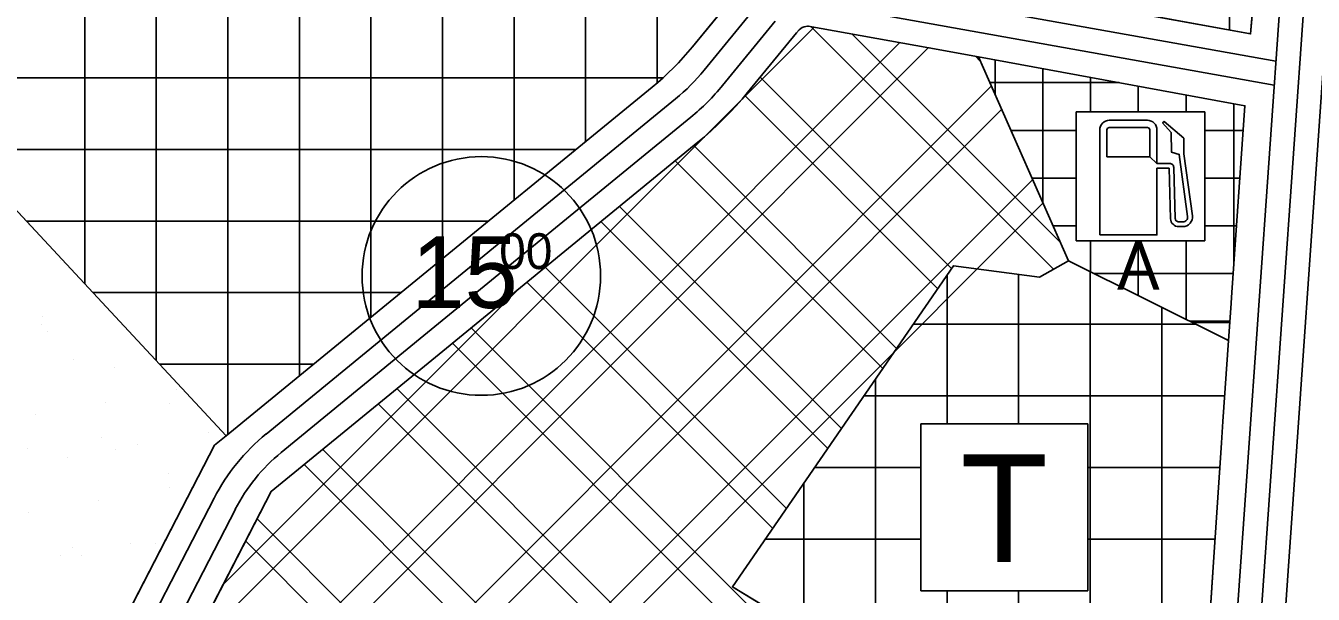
# Model space of a CAD drawing. Extents: x 419109 to 421295, y 4452223 to 4457798.
# Drawn here: x 419929.3 to 420199.2, y 4455078.6 to 4455197.7 of the extents above; entities that cross this region are included whole.
import ezdxf

# ---------------------------------------------------------------- set-up
doc = ezdxf.new("R2010")
doc.units = 0
for name, color, linetype in [('ADAKENARI', 7, 'Continuous'), ('KALDIRIM_FAT', 7, 'Continuous'), ('KD_DAIRE', 7, 'Continuous'), ('KD_YGEN', 7, 'Continuous'), ('PL_AYA_PARK_DINLENME', 7, 'Continuous'), ('PL_BAKIM_AKARYAKIT', 7, 'Continuous'), ('PL_K_DEPOLAMA', 7, 'Continuous'), ('PL_TİCARET', 7, 'Continuous'), ('SEMBOL_FAT', 7, 'Continuous'), ('TRFAT_AKARYAKITSERVİ', 7, 'Continuous'), ('TRFAT_DEPOLAMA', 7, 'Continuous'), ('TRFAT_PARKALANI', 7, 'Continuous'), ('TRFAT_TİCARET', 7, 'Continuous')]:
    doc.layers.add(name, color=color, linetype=linetype)

msp = doc.modelspace()

# ---------------------------------------------------------------- linework, layer by layer
at = {"layer": 'ADAKENARI'}
for p, q in [((420188.54, 4455224.54), (420186.09, 4455195.96)), ((420121.64, 4455207.8), (420186.09, 4455195.96)), ((420069.08, 4455193.26), (420079.57, 4455206.07)), ((420090.86, 4455196.18), (420091.47, 4455196.83)), ((420091.47, 4455196.83), (420091.78, 4455197.08)), ((420091.78, 4455197.08), (420092.11, 4455197.29)), ((420092.11, 4455197.29), (420092.48, 4455197.45)), ((420092.48, 4455197.45), (420092.85, 4455197.56)), ((420092.85, 4455197.56), (420093.2, 4455197.61)), ((420093.2, 4455197.61), (420093.34, 4455197.61)), ((420093.34, 4455197.61), (420118.65, 4455193.09)), ((420080.63, 4455183.68), (420090.86, 4455196.18)), ((420067.13, 4455191), (420068.12, 4455192.12)), ((420068.12, 4455192.12), (420069.08, 4455193.26)), ((420118.65, 4455193.09), (420129.01, 4455191.19)), ((420129.01, 4455191.19), (420147.88, 4455148.42)), ((420129.01, 4455191.19), (420184.88, 4455180.93)), ((420064.01, 4455187.8), (420065.08, 4455188.84)), ((420065.08, 4455188.84), (420066.12, 4455189.91)), ((420066.12, 4455189.91), (420067.13, 4455191)), ((420060.66, 4455184.84), (420061.8, 4455185.8)), ((420061.8, 4455185.8), (420062.92, 4455186.78)), ((420062.92, 4455186.78), (420064.01, 4455187.8)), ((419931.39, 4455154.69), (419902.86, 4455185.32)), ((420006.47, 4455140.52), (420060.66, 4455184.84)), ((420079.49, 4455182.33), (420080.63, 4455183.68)), ((420076.98, 4455179.56), (420078.25, 4455180.93)), ((420078.25, 4455180.93), (420079.49, 4455182.33)), ((420184.88, 4455180.93), (420182.14, 4455141.79)), ((420074.35, 4455176.93), (420075.68, 4455178.23)), ((420075.68, 4455178.23), (420076.98, 4455179.56)), ((420071.58, 4455174.43), (420072.98, 4455175.66)), ((420072.98, 4455175.66), (420074.35, 4455176.93)), ((420015.97, 4455128.91), (420070.23, 4455173.29)), ((420070.23, 4455173.29), (420071.58, 4455174.43)), ((419971.34, 4455111.77), (419931.39, 4455154.69)), ((420141.8, 4455145.02), (420147.88, 4455148.42)), ((420147.88, 4455148.42), (420181.44, 4455131.77)), ((420077.46, 4455080.1), (420123.77, 4455147.42)), ((420123.77, 4455147.42), (420141.8, 4455145.02)), ((420006.47, 4455140.52), (419971.34, 4455111.77)), ((420182.14, 4455141.79), (420181.91, 4455138.55)), ((420181.91, 4455138.55), (420181.44, 4455131.77)), ((420181.44, 4455131.77), (420180.25, 4455114.78)), ((420015.97, 4455128.91), (419980.79, 4455100.13)), ((420180.25, 4455114.78), (420179.97, 4455110.31)), ((419971.34, 4455111.77), (419968.89, 4455109.78)), ((420179.97, 4455110.31), (420178.23, 4455084.23)), ((419968.89, 4455109.78), (419932.03, 4455038.44)), ((419980.79, 4455100.13), (419945.05, 4455030.94)), ((420178.23, 4455084.23), (420176.33, 4455055.75)), ((420135.16, 4455045.14), (420077.46, 4455080.1))]:
    msp.add_line(p, q, dxfattribs=at)
at = {"layer": 'KALDIRIM_FAT'}
for p, q in [((420215.94, 4455540.77), (420179.4, 4455019.05)), ((420220.93, 4455540.45), (420184.39, 4455018.74)), ((420225.92, 4455540.14), (420189.38, 4455018.43)), ((420096.91, 4455207.13), (420191.39, 4455190.25)), ((420096.03, 4455202.21), (420191.04, 4455185.24)), ((420071.54, 4455188.37), (420082.57, 4455201.84)), ((420075.41, 4455185.2), (420086.44, 4455198.67)), ((420009.64, 4455136.65), (420065.55, 4455182.38)), ((420012.8, 4455132.78), (420068.71, 4455178.51)), ((420009.64, 4455136.65), (419979.7, 4455112.15)), ((420012.8, 4455132.78), (419982.86, 4455108.28)), ((419968.81, 4455098.71), (419937.11, 4455037.35)), ((419973.25, 4455096.42), (419941.56, 4455035.06))]:
    msp.add_line(p, q, dxfattribs=at)
for centre, radius, start, end in [((420038.54, 4455215.4), 42.66, 309.2838, 320.6835), ((420038.54, 4455215.4), 47.66, 309.2838, 320.6835), ((420006.71, 4455079.14), 42.66, 129.2845, 152.6835), ((420006.71, 4455079.14), 37.66, 129.2845, 152.6835)]:
    msp.add_arc(centre, radius, start, end, dxfattribs=at)
at = {"layer": 'KD_DAIRE'}
msp.add_circle((420024.82, 4455145.26), 25, dxfattribs=at)
at = {"layer": 'PL_AYA_PARK_DINLENME'}
msp.add_lwpolyline([(419902.86, 4455185.32), (419931.39, 4455154.69), (419971.34, 4455111.77), (419968.89, 4455109.78), (419932.03, 4455038.44), (419931.6, 4455037.58), (419931.19, 4455036.71), (419930.8, 4455035.83), (419930.43, 4455034.94), (419930.09, 4455034.04), (419929.76, 4455033.14), (419929.46, 4455032.22), (419929.18, 4455031.3)], dxfattribs=at)
at = {"layer": 'PL_BAKIM_AKARYAKIT'}
msp.add_lwpolyline([(420182.14, 4455141.79), (420181.91, 4455138.55), (420181.44, 4455131.77), (420147.88, 4455148.42), (420129.01, 4455191.19), (420184.88, 4455180.93)], close=True, dxfattribs=at)
at = {"layer": 'PL_K_DEPOLAMA'}
msp.add_lwpolyline([(420135.16, 4455045.14), (420077.46, 4455080.1), (420123.77, 4455147.42), (420141.8, 4455145.02), (420147.88, 4455148.42), (420129.01, 4455191.19), (420118.65, 4455193.09), (420093.34, 4455197.61), (420093.2, 4455197.61), (420092.85, 4455197.56), (420092.48, 4455197.45), (420092.11, 4455197.29), (420091.78, 4455197.08), (420091.47, 4455196.83), (420090.86, 4455196.18), (420080.63, 4455183.68), (420079.49, 4455182.33), (420078.25, 4455180.93), (420076.98, 4455179.56), (420075.68, 4455178.23), (420074.35, 4455176.93), (420072.98, 4455175.66), (420071.58, 4455174.43), (420070.23, 4455173.29), (420015.97, 4455128.91), (419980.79, 4455100.13), (419945.05, 4455030.94)], dxfattribs=at)
at = {"layer": 'PL_TİCARET'}
for points in [[(419815.33, 4455292.01), (419836.87, 4455182.74), (419902.86, 4455185.32), (419931.39, 4455154.69), (419971.34, 4455111.77), (420006.47, 4455140.52), (420060.66, 4455184.84), (420061.8, 4455185.8), (420062.92, 4455186.78), (420064.01, 4455187.8), (420065.08, 4455188.84), (420066.12, 4455189.91), (420067.13, 4455191), (420068.12, 4455192.12), (420069.08, 4455193.26), (420079.57, 4455206.07)], [(420121.64, 4455207.8), (420186.09, 4455195.96), (420188.54, 4455224.54)]]:
    msp.add_lwpolyline(points, dxfattribs=at)
msp.add_lwpolyline([(420147.88, 4455148.42), (420181.44, 4455131.77), (420180.25, 4455114.78), (420179.97, 4455110.31), (420178.23, 4455084.23), (420176.33, 4455055.75), (420158.29, 4455055.9), (420147.48, 4455061.78), (420143.45, 4455057.26), (420135.16, 4455045.14), (420077.46, 4455080.1), (420123.77, 4455147.42), (420141.8, 4455145.02)], close=True, dxfattribs=at)
at = {"layer": 'SEMBOL_FAT'}
for p, q in [((420149.51, 4455179.63), (420149.51, 4455152.63)), ((420149.51, 4455179.63), (420176.51, 4455179.63)), ((420176.51, 4455179.63), (420176.51, 4455152.63)), ((420149.51, 4455152.63), (420176.51, 4455152.63)), ((420116.94, 4455114.29), (420116.94, 4455079.29)), ((420116.94, 4455114.29), (420151.94, 4455114.29)), ((420151.94, 4455114.29), (420151.94, 4455079.29)), ((420116.94, 4455079.29), (420151.94, 4455079.29))]:
    msp.add_line(p, q, dxfattribs=at)
msp.add_lwpolyline([(420154.46, 4455153.87), (420154.46, 4455175.87), (420154.5, 4455176.26), (420154.61, 4455176.63), (420154.8, 4455176.98), (420155.05, 4455177.28), (420155.35, 4455177.53), (420155.69, 4455177.71), (420156.07, 4455177.83), (420156.46, 4455177.87), (420164.46, 4455177.87), (420164.85, 4455177.83), (420165.22, 4455177.71), (420165.57, 4455177.53), (420165.87, 4455177.28), (420166.12, 4455176.98), (420166.31, 4455176.63), (420166.42, 4455176.26), (420166.46, 4455175.87), (420166.46, 4455168.84), (420164.96, 4455170.23), (420164.96, 4455175.87), (420164.81, 4455176.22), (420164.46, 4455176.37), (420156.46, 4455176.37), (420156.11, 4455176.22), (420155.96, 4455175.87), (420155.96, 4455170.23), (420164.96, 4455170.23), (420166.46, 4455168.84), (420169.13, 4455168.84), (420169.29, 4455168.82), (420169.45, 4455168.78), (420169.59, 4455168.7), (420169.72, 4455168.6), (420169.82, 4455168.48), (420169.9, 4455168.34), (420169.95, 4455168.18), (420169.97, 4455168.02), (420170.3, 4455157.27), (420170.32, 4455157.14), (420170.36, 4455157.01), (420170.43, 4455156.9), (420170.51, 4455156.8), (420170.62, 4455156.71), (420170.73, 4455156.65), (420170.86, 4455156.61), (420170.99, 4455156.6), (420171.88, 4455156.6), (420172.09, 4455156.62), (420172.29, 4455156.69), (420172.48, 4455156.8), (420172.64, 4455156.95), (420172.76, 4455157.12), (420172.84, 4455157.32), (420172.88, 4455157.53), (420172.88, 4455157.75), (420171.13, 4455170.72), (420169.49, 4455171.23), (420169.45, 4455175.29), (420167.64, 4455177.34), (420167.94, 4455177.61), (420172.09, 4455174.11), (420172.12, 4455170.85), (420173.87, 4455157.88), (420173.88, 4455157.45), (420173.8, 4455157.03), (420173.64, 4455156.64), (420173.39, 4455156.29), (420173.08, 4455156), (420172.71, 4455155.78), (420172.3, 4455155.65), (420171.88, 4455155.6), (420170.99, 4455155.6), (420170.67, 4455155.63), (420170.36, 4455155.72), (420170.07, 4455155.88), (420169.82, 4455156.08), (420169.6, 4455156.33), (420169.45, 4455156.61), (420169.34, 4455156.92), (420169.3, 4455157.24), (420168.98, 4455167.84), (420166.46, 4455167.84), (420166.46, 4455153.87)], close=True, dxfattribs=at)
at = {"layer": 'TRFAT_AKARYAKITSERVİ'}
for p, q in [((420132.54, 4455190.54), (420132.54, 4455183.18)), ((420142.54, 4455188.7), (420142.54, 4455160.51)), ((420131.4, 4455185.77), (420158.55, 4455185.77)), ((420152.54, 4455186.87), (420152.54, 4455179.63)), ((420162.54, 4455185.03), (420162.54, 4455179.63)), ((420172.54, 4455183.2), (420172.54, 4455179.63)), ((420182.54, 4455181.36), (420182.54, 4455147.61)), ((420135.81, 4455175.77), (420149.51, 4455175.77)), ((420176.51, 4455175.77), (420184.51, 4455175.77)), ((420140.23, 4455165.77), (420149.51, 4455165.77)), ((420176.51, 4455165.77), (420183.81, 4455165.77)), ((420144.64, 4455155.77), (420149.51, 4455155.77)), ((420176.51, 4455155.77), (420183.11, 4455155.77)), ((420152.54, 4455152.63), (420152.54, 4455146.1)), ((420162.54, 4455152.63), (420162.54, 4455141.14)), ((420172.54, 4455152.63), (420172.54, 4455136.18)), ((420153.23, 4455145.77), (420182.42, 4455145.77)), ((420173.38, 4455135.77), (420181.72, 4455135.77)), ((420173.86, 4455135.53), (420181.7, 4455135.53))]:
    msp.add_line(p, q, dxfattribs=at)
at = {"layer": 'TRFAT_DEPOLAMA'}
for p, q in [((419963.15, 4455065.96), (420094.58, 4455197.39)), ((420093.89, 4455197.52), (420144.74, 4455146.66)), ((419942.79, 4455024.39), (420112.57, 4455194.18)), ((420102.5, 4455195.98), (420146.16, 4455152.32)), ((419939.86, 4455014.4), (420118.57, 4455193.11)), ((420128.39, 4455191.3), (420129.41, 4455190.28)), ((420083.28, 4455186.92), (420123.37, 4455146.83)), ((419959.89, 4455013.21), (420131.72, 4455185.04)), ((420080.09, 4455183.04), (420120.48, 4455142.64)), ((419966.89, 4455013.14), (420133.89, 4455180.14)), ((420069.34, 4455172.57), (420111.84, 4455130.07)), ((420065.45, 4455169.38), (420108.96, 4455125.88)), ((420037.87, 4455062.9), (420140.38, 4455165.42)), ((420044.94, 4455062.9), (420142.54, 4455160.51)), ((420053.79, 4455159.84), (420100.31, 4455113.31)), ((420049.9, 4455156.66), (420097.43, 4455109.13)), ((420038.23, 4455147.11), (420088.78, 4455096.56)), ((419970.7, 4455080.59), (420032.71, 4455142.6)), ((420034.34, 4455143.93), (420085.9, 4455092.37)), ((420022.67, 4455134.39), (420125.86, 4455031.2)), ((420018.78, 4455131.21), (420123.03, 4455026.95)), ((420007.11, 4455121.66), (420114.55, 4455014.22)), ((420003.22, 4455118.48), (420110.08, 4455011.62)), ((419991.56, 4455108.93), (420037.58, 4455062.9)), ((419987.67, 4455105.75), (420030.51, 4455062.9)), ((419977.82, 4455094.38), (420016.14, 4455056.07)), ((419975.42, 4455089.72), (420016.14, 4455049))]:
    msp.add_line(p, q, dxfattribs=at)
at = {"layer": 'TRFAT_PARKALANI'}
for p, q in [((419936.57, 4455148.49), (419936.57, 4455148.49)), ((419932.57, 4455135), (419932.57, 4455135)), ((419932.76, 4455136.78), (419932.76, 4455136.78)), ((419933.97, 4455133.72), (419933.97, 4455133.72)), ((419939.42, 4455127.8), (419939.42, 4455127.8)), ((419947.87, 4455126.19), (419947.87, 4455126.19)), ((419960.86, 4455121.43), (419960.86, 4455121.43)), ((419946.08, 4455118.83), (419946.08, 4455118.83)), ((419959.52, 4455118.45), (419959.52, 4455118.45)), ((419931.31, 4455116.22), (419931.31, 4455116.22)), ((419945.27, 4455111.41), (419945.27, 4455111.41)), ((419967.52, 4455112.45), (419967.52, 4455112.45)), ((419929.63, 4455109.1), (419929.63, 4455109.1)), ((419948.03, 4455108.81), (419948.03, 4455108.81)), ((419952.74, 4455109.85), (419952.74, 4455109.85)), ((419937.97, 4455107.24), (419937.97, 4455107.24)), ((419959.17, 4455103.89), (419959.17, 4455103.89)), ((419959.4, 4455100.87), (419959.4, 4455100.87)), ((419944.63, 4455098.26), (419944.63, 4455098.26)), ((419929.86, 4455095.66), (419929.86, 4455095.66)), ((419951.29, 4455089.28), (419951.29, 4455089.28)), ((419956.57, 4455089.11), (419956.57, 4455089.11)), ((419936.52, 4455086.68), (419936.52, 4455086.68)), ((419939.13, 4455088.29), (419939.13, 4455088.29)), ((419940.93, 4455086.79), (419940.93, 4455086.79))]:
    msp.add_line(p, q, dxfattribs=at)
at = {"layer": 'TRFAT_TİCARET'}
for p, q in [((420061.68, 4455185.7), (420061.68, 4455772.5)), ((420046.68, 4455173.41), (420046.68, 4455741.21)), ((420031.68, 4455161.13), (420031.68, 4455713.07)), ((420016.68, 4455148.86), (420016.68, 4455685.9)), ((420001.68, 4455136.59), (420001.68, 4455658.72)), ((419986.68, 4455124.32), (419986.68, 4455631.54)), ((419971.68, 4455112.05), (419971.68, 4455604.36)), ((419956.68, 4455127.52), (419956.68, 4455577.19)), ((419941.68, 4455143.64), (419941.68, 4455558.89)), ((420181.68, 4455196.77), (420181.68, 4455506.05)), ((419836.08, 4455186.77), (420062.91, 4455186.77)), ((419915.48, 4455171.77), (420044.68, 4455171.77)), ((419929.45, 4455156.77), (420026.35, 4455156.77)), ((420122.46, 4455114.29), (420122.46, 4455145.51)), ((420137.46, 4455114.29), (420137.46, 4455145.6)), ((420152.46, 4455059.07), (420152.46, 4455146.15)), ((419943.41, 4455141.77), (420008.01, 4455141.77)), ((420167.46, 4455055.82), (420167.46, 4455138.7)), ((420115.32, 4455135.14), (420174.65, 4455135.14)), ((419957.38, 4455126.77), (419989.67, 4455126.77)), ((420107.46, 4455061.92), (420107.46, 4455123.71)), ((420105, 4455120.14), (420180.62, 4455120.14)), ((420094.69, 4455105.14), (420116.94, 4455105.14)), ((420151.94, 4455105.14), (420179.62, 4455105.14)), ((420092.46, 4455071.01), (420092.46, 4455101.9)), ((420084.37, 4455090.14), (420116.94, 4455090.14)), ((420151.94, 4455090.14), (420178.62, 4455090.14)), ((420122.46, 4455052.83), (420122.46, 4455079.29)), ((420137.46, 4455048.5), (420137.46, 4455079.29))]:
    msp.add_line(p, q, dxfattribs=at)

# ---------------------------------------------------------------- texts
at = {"layer": 'KD_YGEN'}
for s, height, p in [('15', 15, (420010.16, 4455138.56)), ('00', 7.5, (420028.56, 4455146.71))]:
    msp.add_text(s, height=height, dxfattribs=at).set_placement(p)
at = {"layer": 'SEMBOL_FAT'}
for s, height, p in [('A', 10, (420158.09, 4455142.42)), ('T', 22.5, (420125.23, 4455085.36))]:
    msp.add_text(s, height=height, dxfattribs=at).set_placement(p)

doc.saveas('drawing.dxf')
